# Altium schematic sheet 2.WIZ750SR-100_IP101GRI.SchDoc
size A4; Team: Wiki
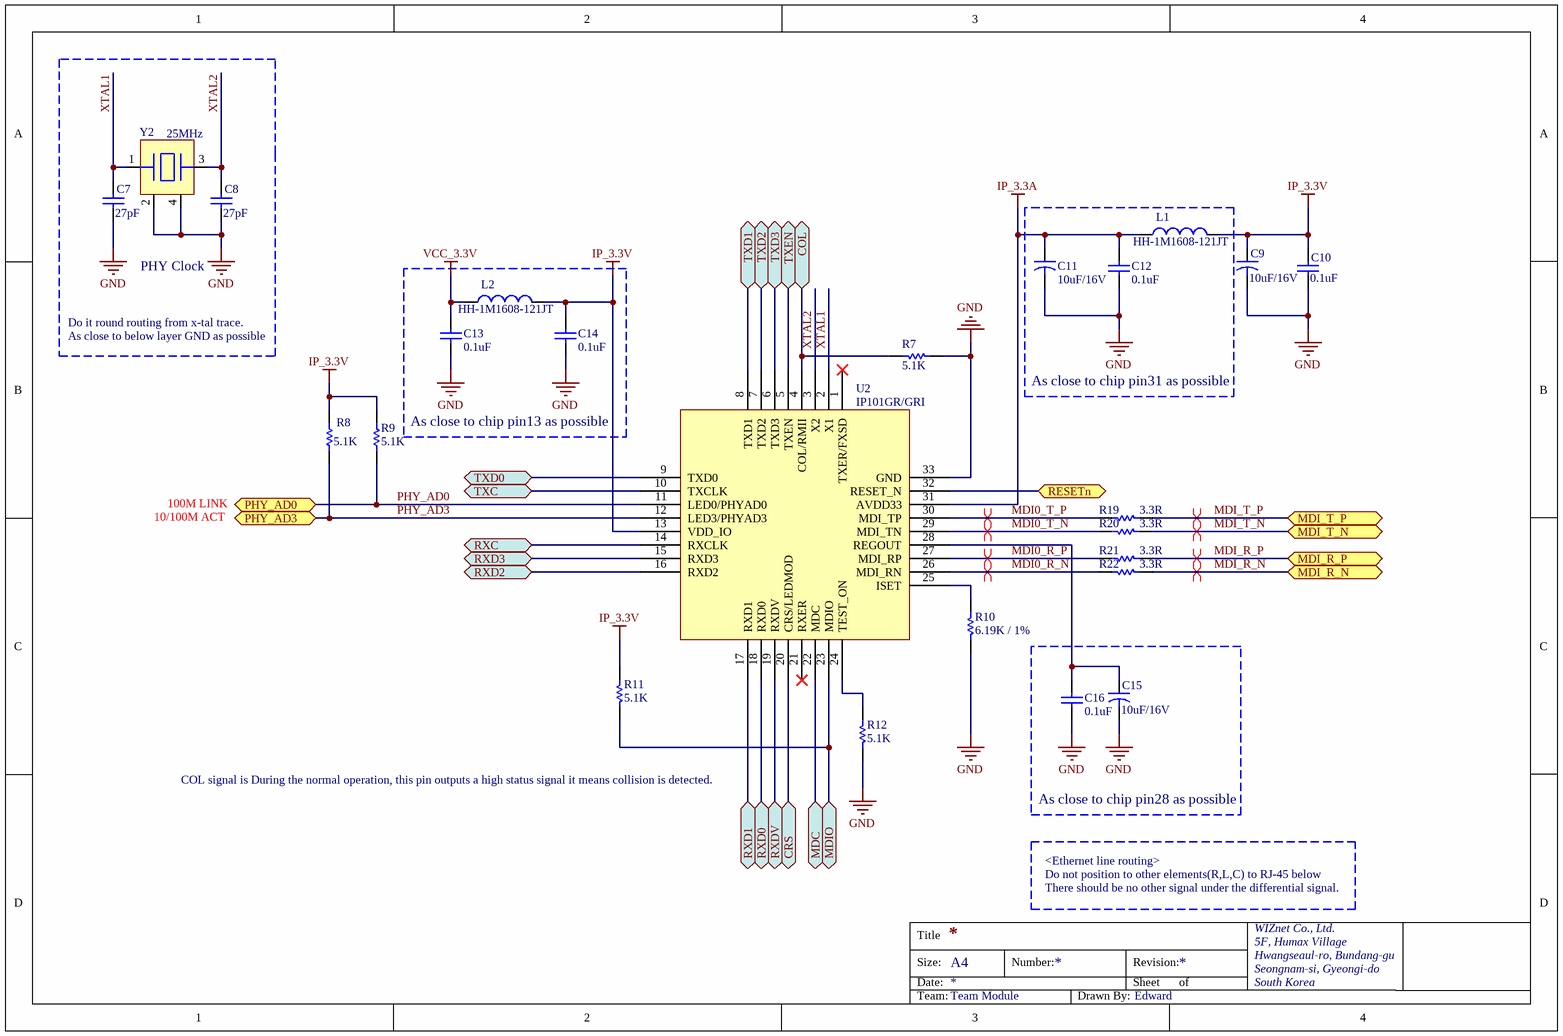
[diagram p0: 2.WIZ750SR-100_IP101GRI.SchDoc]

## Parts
C7  27pF  [CAP-0402]
C8  27pF  [CAP-0402]
C9  10uF/16V  [CAP-A Size]
C10  0.1uF  [CAP-0402]
C11  10uF/16V  [CAP-A Size]
C12  0.1uF  [CAP-0402]
C13  0.1uF  [CAP-0402]
C14  0.1uF  [CAP-0402]
C15  10uF/16V  [CAP-A Size]
C16  0.1uF  [CAP-0402]
L1  HH-1M1608-121JT  [IND-0603]
L2  HH-1M1608-121JT  [IND-0603]
R7  5.1K  [RES-0402]
R8  5.1K  [RES-0402]
R9  5.1K  [RES-0402]
R10  6.19K / 1%  [RES-0402]
R11  5.1K  [RES-0402]
R12  5.1K  [RES-0402]
R19  3.3R  [RES-0402]
R20  3.3R  [RES-0402]
R21  3.3R  [RES-0402]
R22  3.3R  [RES-0402]
U2  IP101GR/GRI  [QFN32(0.4/4X4)]
Y2  25MHz  [OSC-82J0626]

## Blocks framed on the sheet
PHY Clock: C7 C8 Y2
As close to chip pin31 as possible: C11 C12 L1
As close to chip pin13 as possible: C13 C14 L2
As close to chip pin28 as possible: C15 C16

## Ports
COL, CRS, MDC, MDI_R_N, MDI_R_P, MDI_T_N, MDI_T_P, MDIO, PHY_AD0, PHY_AD3, RESETn, RXC, RXD0, RXD1, RXD2, RXD3, RXDV, TXC, TXD0, TXD1, TXD2, TXD3, TXEN

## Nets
GND: C7.1 C8.1 C9.2 C10.1 C11.2 C12.1 C13.1 C14.2 C15.2 C16.1 R7.1 R10.1 R12.1 U2.33(GND) Y2.2 Y2.4
IP_3.3A: C11.1 C12.2 L1.1 U2.31(AVDD33)
IP_3.3V: C9.1 C10.2 C14.1 L1.2 L2.2 R8.1 R9.1 R11.2 U2.13(VDD_IO)
VCC_3.3V: C13.2 L2.1
COL: R7.2 U2.4(COL/RMII) ; port COL
CRS: U2.20(CRS/LEDMOD) ; port CRS
MDC: U2.22(MDC) ; port MDC
MDI0_R_N: R22.2 U2.26(MDI_RN)
MDI0_R_P: R21.2 U2.27(MDI_RP)
MDI0_T_N: R20.2 U2.29(MDI_TN)
MDI0_T_P: R19.2 U2.30(MDI_TP)
MDI_R_N: R22.1 ; port MDI_R_N
MDI_R_P: R21.1 ; port MDI_R_P
MDI_T_N: R20.1 ; port MDI_T_N
MDI_T_P: R19.1 ; port MDI_T_P
MDIO: R11.1 U2.23(MDIO) ; port MDIO
PHY_AD0: R9.2 U2.11(LED0/PHYAD0) ; port PHY_AD0
PHY_AD3: R8.2 U2.12(LED3/PHYAD3) ; port PHY_AD3
RESETn: U2.32(RESET_N) ; port RESETn
RXC: U2.14(RXCLK) ; port RXC
RXD0: U2.18(RXD0) ; port RXD0
RXD1: U2.17(RXD1) ; port RXD1
RXD2: U2.16(RXD2) ; port RXD2
RXD3: U2.15(RXD3) ; port RXD3
RXDV: U2.19(RXDV) ; port RXDV
TXC: U2.10(TXCLK) ; port TXC
TXD0: U2.9(TXD0) ; port TXD0
TXD1: U2.8(TXD1) ; port TXD1
TXD2: U2.7(TXD2) ; port TXD2
TXD3: U2.6(TXD3) ; port TXD3
TXEN: U2.5(TXEN) ; port TXEN
XTAL1: C7.2 U2.2(X1) Y2.1
XTAL2: C8.2 U2.3(X2) Y2.3
NetC15_1: C15.1 C16.2 U2.28(REGOUT)
NetR10_2: R10.2 U2.25(ISET)
NetR12_2: R12.2 U2.24(TEST_ON)

Not connected (* = marked no-connect by the designer): U2 1(TXER/FXSD)* 21(RXER)*

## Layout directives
differential pair: MDI0_R_N, MDI0_R_P, MDI0_T_N, MDI0_T_P, MDI_R_N, MDI_R_P, MDI_T_N, MDI_T_P

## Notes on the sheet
- Do it round routing from x-tal trace.
- As close to below layer GND as possible
- 10/100M ACT
- 100M LINK
- (near R12) COL signal is During the normal operation, this pin outputs a high status signal it means collision is detected.
- <Ethernet line routing>
- Do not position to other elements(R,L,C) to RJ-45 below
- There should be no other signal under the differential signal.

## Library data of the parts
C7 C8 C10 C12-C14 C16 = CAP-0402: Ceramic CAP 0402(1005)
C9 C11 C15 = CAP-A Size: Tantla CAP A Size EIA/IECQ 3216
L1 L2 = IND-0603: Inductor 0603(1608)
R7 R10-R12 R19-R22 = RES-0402
R8 R9 = RES-0603: RES-0402
U2 = IP101GR/GRI: Pakage: VQFN-32
Y2 = OSC-82J0626-25MHz: X-tal 25MHz,3.2x2.5 SMD, CL=18pF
